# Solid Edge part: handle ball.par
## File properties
Title: Handle Ball
Author: Abhinva Rai
Template: Normal.par
Last saved by: Robert a Rhodes jr
Revision: 9
Application: Solid Edge
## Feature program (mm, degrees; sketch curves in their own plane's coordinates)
sketch for "unnamed RevolvedProtrusion 1" plane through (0, 0, 0) normal (0, -1, 0) x-axis (1, 0, 0)
  arc centre (0, 0) radius 9.525 from (0, 9.525) to (0, -9.525) cw
  line (0, 9.525) -> (0, -9.525)
revolve "unnamed RevolvedProtrusion 1" add finite 360 deg
sketch for "unnamed Cutout 1" plane through (0, 0, 0) normal (0, -1, 0) x-axis (1, 0, 0)
  circle centre (0, 0) radius 3.9751
extrude "unnamed Cutout 1" cut finite 50.8 symmetric
sketch for "unnamed Cutout 2" plane through (0, 0, 0) normal (0, 0, 1) x-axis (1, 0, 0)
  circle centre (0, 0) radius 1.905
extrude "unnamed Cutout 2" cut finite 50.8 symmetric
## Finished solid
Body 1: solid body, 4 faces, 6 edges, 0 vertices.
  Faces by surface: cylinder 3, sphere 1
  Edges by curve: circle 4, intersection 2
Bounding box of the edges (mm; curved faces can reach further): 7.950 x 17.312 x 18.665, from (-3.9751, -8.6559, -9.3326) to (3.9751, 8.6559, 9.3326).
Cylindrical faces by radius (mm): R1.905 x2, R3.9751 x1
Spherical faces by radius (mm): R9.525 x1
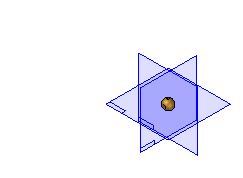
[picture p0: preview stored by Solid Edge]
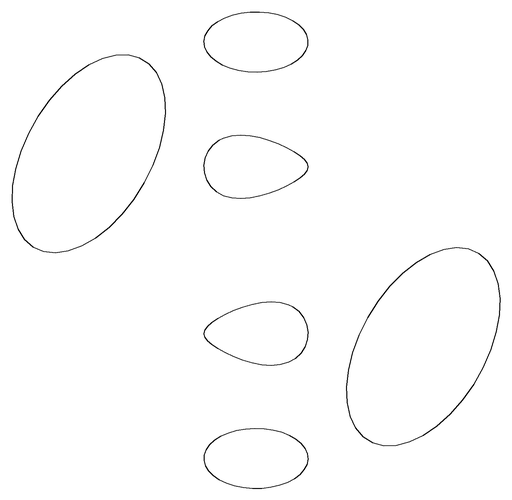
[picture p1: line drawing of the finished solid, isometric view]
